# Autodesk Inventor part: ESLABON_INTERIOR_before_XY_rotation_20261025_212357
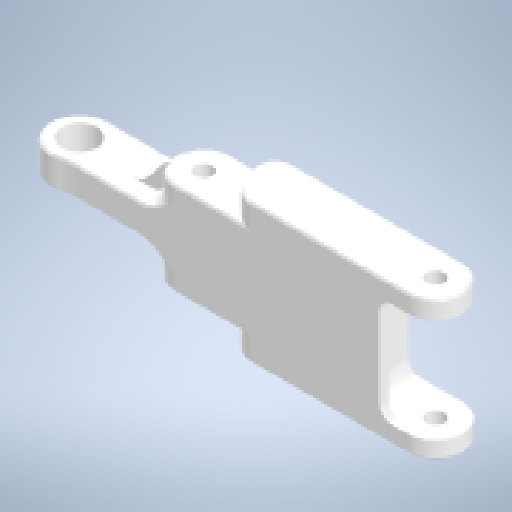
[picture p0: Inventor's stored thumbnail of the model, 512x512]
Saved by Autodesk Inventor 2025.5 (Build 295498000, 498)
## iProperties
Created: 2026-10
Part Number: ESLABON_INTERIOR_before_XY_rotation_20261025_212357
Material: Genérico
Description: Eslabón interior
Document SubType Name: Modeling
Designer: Luis MuÃ±oz
Density: 1 g/cm^3
Appearance: Valor por defecto
Project: TESIS 2 - Plataforma mecatrÃ³nica preventiva desacoplada
Mass: 5.56027 g
Surface Area: 46.7917 cm^2
Volume: 5.56027 cm^3
Sending System: ONSHAPE BY PTC INC, 1.194
Preprocessor: ST-DEVELOPER v20
Material_Fabricacion: PLA
Title: EslabÃ³n interior
Revision Number: 00
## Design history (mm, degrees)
feature "Internal_Rod"
feature "Rotacion al plano XY (90 grados eje X)"
feature "Alineacion medida cara principal a XY"
feature "Cara principal sobre plano XY (Z=0)"
node "Sólido1"
other parameters: "d0" = 15.70796, "d1" = 0, "d2" = 30 deg, "d3" = 0, "d4" = 0, "d5" = 23.39583
